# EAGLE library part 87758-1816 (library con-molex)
18 Pin - 2mm Dual Row Single Wafer, Vertical T/H HDR Source: http://www.molex.com/pdm_docs/sd/877580616_sd.pdf
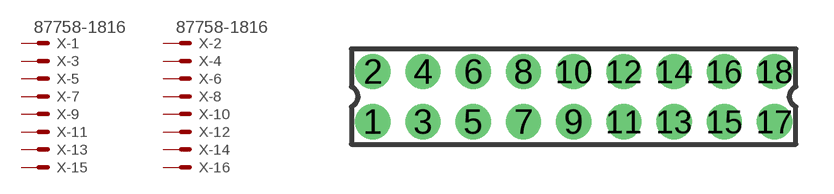
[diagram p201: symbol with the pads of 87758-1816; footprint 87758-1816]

Designator prefix X; gates -1=MV -2=MV -3=M -4=M -5=M -6=M -7=M -8=M -9=M -10=M -11=M -12=M -13=M -14=M -15=M -16=M -17=M -18=M

## 87758-1816 (MPN: 87758-1816; OC_FARNELL: unknown; OC_NEWARK: 25M5675)  [87758-1816]
1  -1:S  pas
2  -2:S  pas
3  -3:S  pas
4  -4:S  pas
5  -5:S  pas
6  -6:S  pas
7  -7:S  pas
8  -8:S  pas
9  -9:S  pas
10  -10:S  pas
11  -11:S  pas
12  -12:S  pas
13  -13:S  pas
14  -14:S  pas
15  -15:S  pas
16  -16:S  pas
17  -17:S  pas
18  -18:S  pas

## Footprint 87758-1816 (pad centres in mm)
18 Pin - 2mm Dual Row Single Wafer, Vertical T/H HDR Source: http://www.molex.com/pdm_docs/sd/877580616_sd.pdf
drill 0.9 pad 1.27 round: 1 -8,-1; 2 -8,1; 3 -6,-1; 4 -6,1; 5 -4,-1; 6 -4,1; 7 -2,-1; 8 -2,1; 9 0,-1; 10 0,1; 11 2,-1; 12 2,1; 13 4,-1; 14 4,1; 15 6,-1; 16 6,1; 17 8,-1; 18 8,1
